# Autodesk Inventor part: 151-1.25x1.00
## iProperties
Created: 2007-07
Part Number: 151-1.25x1.00
Document SubType Name: Modeling
Designer: btaylor
Density: 1 g/cm^3
Author: btaylor
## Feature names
1. Loft1
2. Extrusion1
3. Extrusion2
4. Fillet1
5. Fillet2
6. Extrusion3
7. Extrusion4
8. Chamfer1
9. Chamfer2
10. Fillet3
11. Fillet4
12. Loft2
13. Fillet5
14. Fillet6
